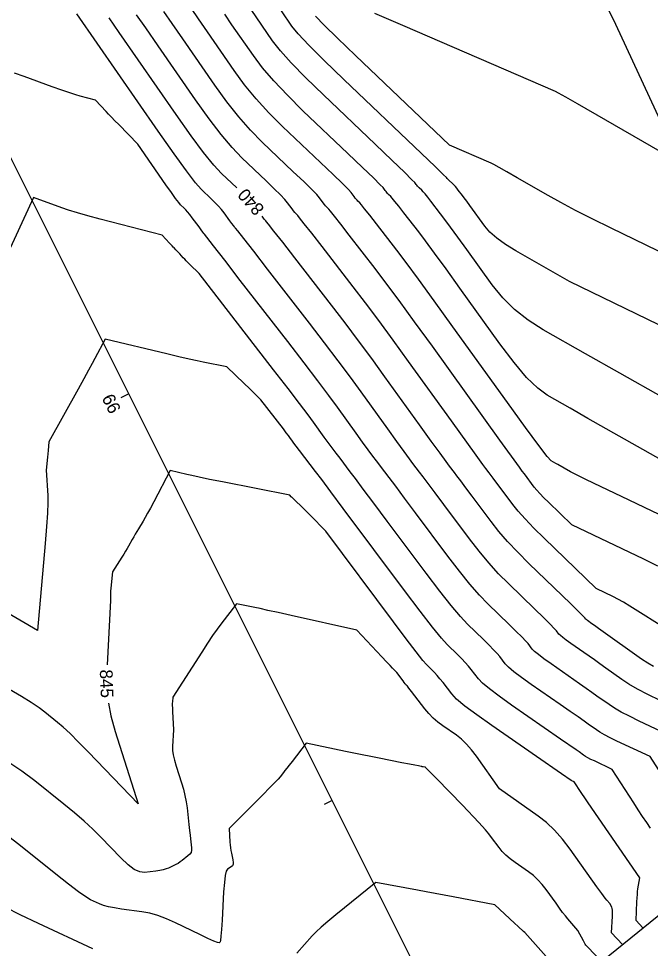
# Model space of a CAD drawing. Extents: x 1715724 to 1716561, y 394063 to 395906.
# Drawn here: x 1716399.3 to 1716468.8, y 394300.9 to 394403.2 of the extents above; entities that cross this region are included whole.
import ezdxf

# ---------------------------------------------------------------- set-up
doc = ezdxf.new("R2010")
doc.units = 0
for name, color, linetype in [('DT_X_Contour_Major', 7, 'Continuous'), ('DT_X_Contour_Minor', 7, 'Continuous'), ('DT_X_TIN_Hull', 7, 'Continuous'), ('GE_P_CL_10', 7, 'Continuous')]:
    doc.layers.add(name, color=color, linetype=linetype)

msp = doc.modelspace()

# ---------------------------------------------------------------- linework, layer by layer
at = {"layer": 'DT_X_Contour_Major'}
for points in [[(1716484.64, 394353.28), (1716465.41, 394364.13), (1716461.63, 394366.28), (1716456.98, 394368.93), (1716455.33, 394369.99), (1716453.84, 394371.16), (1716452.53, 394372.44), (1716451.39, 394373.85), (1716448.58, 394377.75), (1716447.61, 394379.09), (1716446.8, 394380.2), (1716446.16, 394381.06), (1716445.69, 394381.69), (1716444.64, 394383.05), (1716444.28, 394383.5), (1716443.99, 394383.86), (1716443.78, 394384.11), (1716443.63, 394384.27), (1716443.35, 394384.54), (1716443.24, 394384.64), (1716443.15, 394384.73), (1716443.08, 394384.82), (1716443.01, 394384.9), (1716442.86, 394385.11), (1716442.54, 394385.43), (1716441.71, 394386.24), (1716440.35, 394387.54), (1716438.48, 394389.33), (1716432.8, 394394.75), (1716430.85, 394396.64), (1716429.27, 394398.27), (1716428.06, 394399.62), (1716427.21, 394400.71), (1716424.84, 394404.14)], [(1716423.26, 394384.52), (1716421.58, 394386.12), (1716420.73, 394387.04), (1716419.62, 394388.42), (1716418.25, 394390.27), (1716416.61, 394392.59), (1716410.33, 394401.63), (1716409.21, 394403.25)], [(1716469.13, 394331.87), (1716468.51, 394332.23), (1716467.82, 394332.69), (1716467.04, 394333.23), (1716464.12, 394335.32), (1716463.09, 394336.06), (1716462.79, 394336.27), (1716462.2, 394336.68), (1716462, 394336.82), (1716461.85, 394336.94), (1716461.74, 394337.03), (1716461.67, 394337.1), (1716461.56, 394337.24), (1716461.36, 394337.45), (1716460.84, 394337.96), (1716460.02, 394338.76), (1716455.41, 394343.21), (1716454.18, 394344.44), (1716453.07, 394345.62), (1716452.1, 394346.74), (1716451.25, 394347.81), (1716449.18, 394350.6), (1716448.47, 394351.54), (1716447.91, 394352.3), (1716447.49, 394352.86), (1716447.21, 394353.22), (1716446.66, 394353.93), (1716446.31, 394354.42), (1716445.64, 394355.33), (1716444.67, 394356.68), (1716443.39, 394358.45), (1716439.57, 394363.76), (1716438.12, 394365.75), (1716436.66, 394367.72), (1716435.18, 394369.68), (1716433.68, 394371.64), (1716429.65, 394376.84), (1716428.32, 394378.55), (1716427.36, 394379.78), (1716426.77, 394380.53), (1716426.55, 394380.81), (1716426.45, 394380.9), (1716426.39, 394380.97), (1716426.28, 394381.1), (1716426.13, 394381.3), (1716426.06, 394381.4)], [(1716467.97, 394303.11), (1716467.21, 394303.92), (1716467.3, 394305.99), (1716467.32, 394306.42), (1716467.35, 394306.79), (1716467.38, 394307.12), (1716467.42, 394307.4), (1716467.61, 394308.61), (1716461.95, 394316.88), (1716460.87, 394318.46), (1716460.68, 394318.73), (1716460.4, 394319.17), (1716460.13, 394319.3), (1716460.06, 394319.33), (1716459.02, 394320.05), (1716456.24, 394321.98), (1716451.32, 394325.39), (1716449.67, 394326.56), (1716448.38, 394327.53), (1716447.46, 394328.3), (1716446.92, 394328.86), (1716445.97, 394330.1), (1716445.62, 394330.53), (1716445.31, 394330.9), (1716445.03, 394331.22), (1716444.78, 394331.47), (1716444.16, 394332.08), (1716443.75, 394332.54), (1716443.01, 394333.49), (1716441.92, 394334.91), (1716440.5, 394336.8), (1716433.06, 394346.77), (1716431.35, 394348.52), (1716431.01, 394348.87), (1716430.72, 394349.16), (1716430.48, 394349.4), (1716430.29, 394349.58), (1716429.85, 394349.99), (1716429.71, 394350.13), (1716429.59, 394350.24), (1716429.51, 394350.31), (1716429.47, 394350.36), (1716429.39, 394350.43), (1716429.36, 394350.46), (1716429.32, 394350.49), (1716429.29, 394350.52), (1716429.26, 394350.55), (1716429.1, 394350.71), (1716421.71, 394352.18), (1716420.28, 394352.46), (1716419.14, 394352.7), (1716418.31, 394352.87), (1716417.77, 394352.99), (1716415.95, 394353.42), (1716414.13, 394349.99), (1716413.76, 394349.31), (1716413.44, 394348.73), (1716413.18, 394348.26), (1716412.96, 394347.88), (1716412.45, 394347.03), (1716412.26, 394346.72), (1716412.09, 394346.42), (1716411.92, 394346.13), (1716411.76, 394345.85), (1716411.36, 394345.13), (1716411.21, 394344.85), (1716411.03, 394344.55), (1716410.83, 394344.24), (1716410.62, 394343.9), (1716409.59, 394342.28), (1716409.42, 394340.5), (1716409.38, 394340.16), (1716409.36, 394339.88), (1716409.35, 394339.69), (1716409.35, 394339.56), (1716409.37, 394339.14), (1716408.99, 394332.05)], [(1716409.14, 394327.86), (1716409.4, 394326.45), (1716409.87, 394324.74), (1716412.43, 394316.76), (1716406.95, 394322.45), (1716405.86, 394323.57), (1716404.92, 394324.49), (1716404.15, 394325.21), (1716403.54, 394325.73), (1716402.14, 394326.86), (1716401.5, 394327.33), (1716400.64, 394327.9), (1716399.56, 394328.56), (1716398.27, 394329.33)]]:
    msp.add_lwpolyline(points, dxfattribs=at)
at = {"layer": 'DT_X_Contour_Minor'}
for points in [[(1716469.62, 394342.92), (1716468.05, 394343.68), (1716460.13, 394347.46), (1716457.56, 394349.94), (1716457.05, 394350.44), (1716456.62, 394350.89), (1716456.28, 394351.28), (1716456.01, 394351.61), (1716454.93, 394353.06), (1716454.69, 394353.37), (1716454.38, 394353.8), (1716452.22, 394356.79), (1716444.8, 394367.1), (1716442.83, 394369.81), (1716441.13, 394372.15), (1716439.67, 394374.1), (1716438.48, 394375.66), (1716435.64, 394379.32), (1716434.71, 394380.53), (1716434.02, 394381.41), (1716433.58, 394381.96), (1716433.38, 394382.19), (1716433.21, 394382.36), (1716433.13, 394382.44), (1716433.03, 394382.56), (1716432.91, 394382.71), (1716432.77, 394382.9), (1716432.36, 394383.45), (1716432.06, 394383.79), (1716431.49, 394384.38), (1716430.63, 394385.22), (1716429.49, 394386.31), (1716426.07, 394389.57), (1716424.78, 394390.88), (1716423.48, 394392.36), (1716422.17, 394394.01), (1716420.85, 394395.84), (1716417.32, 394400.93), (1716416.14, 394402.63), (1716415.25, 394403.92)], [(1716472.3, 394347.38), (1716465.61, 394350.57), (1716463.37, 394351.64), (1716461.69, 394352.45), (1716460.57, 394353.01), (1716459.99, 394353.3), (1716458.59, 394354.09), (1716458.39, 394354.2), (1716457.86, 394354.51), (1716457.44, 394354.98), (1716456.51, 394356.2), (1716455.05, 394358.18), (1716453.06, 394360.93), (1716447.06, 394369.26), (1716444.99, 394372.12), (1716443.27, 394374.48), (1716441.9, 394376.33), (1716440.88, 394377.67), (1716438.64, 394380.56), (1716437.9, 394381.52), (1716437.34, 394382.23), (1716436.98, 394382.68), (1716436.8, 394382.88), (1716436.59, 394383.08), (1716436.5, 394383.17), (1716436.41, 394383.28), (1716436.3, 394383.41), (1716436.18, 394383.57), (1716435.86, 394384.01), (1716435.56, 394384.34), (1716434.89, 394385), (1716433.87, 394385.99), (1716432.48, 394387.32), (1716428.31, 394391.3), (1716426.8, 394392.8), (1716425.41, 394394.33), (1716424.13, 394395.88), (1716422.97, 394397.46), (1716420.03, 394401.7), (1716419.04, 394403.13), (1716418.27, 394404.25)], [(1716469.7, 394369.48), (1716459.88, 394374.24), (1716453.99, 394377.6), (1716452.83, 394378.31), (1716451.87, 394379), (1716451.11, 394379.66), (1716450.56, 394380.31), (1716448.92, 394382.58), (1716448.57, 394383.06), (1716448.29, 394383.43), (1716448.09, 394383.7), (1716447.63, 394384.29), (1716447.47, 394384.49), (1716447.32, 394384.67), (1716447.18, 394384.83), (1716447.05, 394384.96), (1716446.61, 394385.37), (1716446.53, 394385.46), (1716446.47, 394385.52), (1716446.43, 394385.57), (1716446.36, 394385.66), (1716446.03, 394385.98), (1716445.11, 394386.87), (1716443.59, 394388.32), (1716435.04, 394396.47), (1716432.87, 394398.56), (1716431.2, 394400.24), (1716430.02, 394401.49), (1716429.33, 394402.33), (1716428.17, 394404.01)], [(1716472.03, 394387.27), (1716460.77, 394393.76), (1716459.47, 394394.5), (1716458.67, 394394.96), (1716458.35, 394395.13), (1716441.55, 394402.39), (1716438.45, 394403.73)], [(1716469.88, 394328.13), (1716468.52, 394328.79), (1716467.36, 394329.4), (1716466.4, 394329.95), (1716465.64, 394330.45), (1716463.89, 394331.71), (1716463.24, 394332.17), (1716462.63, 394332.61), (1716462.04, 394333.02), (1716461.48, 394333.41), (1716460.03, 394334.42), (1716459.53, 394334.77), (1716459.15, 394335.06), (1716458.88, 394335.28), (1716458.72, 394335.45), (1716458.44, 394335.81), (1716458.21, 394336.07), (1716457.74, 394336.54), (1716457.02, 394337.25), (1716456.06, 394338.19), (1716453.16, 394340.99), (1716452.08, 394342.08), (1716451, 394343.27), (1716449.94, 394344.55), (1716448.87, 394345.92), (1716446.06, 394349.69), (1716445.1, 394350.98), (1716444.34, 394352), (1716443.77, 394352.75), (1716443.39, 394353.25), (1716442.65, 394354.22), (1716442.27, 394354.73), (1716441.69, 394355.53), (1716440.89, 394356.62), (1716439.89, 394358.01), (1716436.95, 394362.09), (1716435.77, 394363.71), (1716434.43, 394365.51), (1716432.93, 394367.48), (1716431.28, 394369.63), (1716426.65, 394375.59), (1716425.13, 394377.56), (1716424.04, 394378.96), (1716423.37, 394379.82), (1716423.13, 394380.11), (1716423.07, 394380.18), (1716423.02, 394380.24), (1716422.91, 394380.38), (1716422.74, 394380.6), (1716422.52, 394380.9), (1716421.86, 394381.8), (1716421.58, 394382.15), (1716421.26, 394382.51), (1716420.9, 394382.9), (1716420.49, 394383.3), (1716419.34, 394384.4), (1716418.72, 394385.1), (1716417.73, 394386.4), (1716416.37, 394388.28), (1716414.63, 394390.76), (1716405.67, 394403.67)], [(1716469.85, 394336.42), (1716467.4, 394337.98), (1716466.54, 394338.51), (1716465.81, 394338.95), (1716465.21, 394339.3), (1716464.74, 394339.54), (1716462.82, 394340.45), (1716457.09, 394345.99), (1716455.96, 394347.11), (1716455, 394348.11), (1716454.23, 394348.97), (1716453.63, 394349.71), (1716451.48, 394352.6), (1716451.03, 394353.19), (1716450.68, 394353.65), (1716450.34, 394354.11), (1716449.6, 394355.14), (1716446.89, 394358.9), (1716442.18, 394365.43), (1716440.48, 394367.78), (1716438.89, 394369.93), (1716437.43, 394371.89), (1716436.08, 394373.65), (1716432.65, 394378.08), (1716431.51, 394379.54), (1716430.69, 394380.59), (1716430.17, 394381.25), (1716429.97, 394381.5), (1716429.83, 394381.63), (1716429.76, 394381.7), (1716429.66, 394381.83), (1716429.52, 394382.01), (1716429.35, 394382.23), (1716428.86, 394382.9), (1716428.57, 394383.24), (1716428.08, 394383.76), (1716427.38, 394384.44), (1716426.49, 394385.31), (1716423.82, 394387.85), (1716422.76, 394388.96), (1716421.55, 394390.39), (1716420.21, 394392.14), (1716418.73, 394394.21), (1716414.6, 394400.16), (1716413.24, 394402.13), (1716412.23, 394403.58)], [(1716470.8, 394354.14), (1716461.91, 394359.16), (1716459.95, 394360.28), (1716457.42, 394361.72), (1716456.39, 394362.48), (1716455.17, 394363.68), (1716453.79, 394365.31), (1716452.22, 394367.39), (1716447.82, 394373.5), (1716446.3, 394375.61), (1716445.04, 394377.34), (1716444.03, 394378.7), (1716443.29, 394379.68), (1716441.64, 394381.8), (1716441.09, 394382.51), (1716440.67, 394383.04), (1716440.38, 394383.4), (1716440.22, 394383.57), (1716439.97, 394383.81), (1716439.87, 394383.9), (1716439.78, 394384.01), (1716439.69, 394384.12), (1716439.6, 394384.23), (1716439.36, 394384.56), (1716439.05, 394384.88), (1716438.3, 394385.62), (1716437.11, 394386.77), (1716435.48, 394388.32), (1716430.55, 394393.02), (1716428.83, 394394.72), (1716427.34, 394396.3), (1716426.1, 394397.75), (1716425.09, 394399.08), (1716422.74, 394402.47), (1716421.94, 394403.63)], [(1716479.48, 394372.72), (1716474.68, 394375.13), (1716464.46, 394380.09), (1716462.39, 394381.11), (1716460.55, 394382.05), (1716458.93, 394382.91), (1716457.54, 394383.68), (1716454.12, 394385.65), (1716452.99, 394386.3), (1716452.13, 394386.78), (1716451.56, 394387.1), (1716451.27, 394387.25), (1716446.69, 394389.23), (1716436.33, 394399.1), (1716434.36, 394400.99), (1716432.89, 394402.43), (1716431.92, 394403.42)], [(1716472.93, 394323.35), (1716467.54, 394325.88), (1716466.47, 394326.4), (1716465.56, 394326.87), (1716464.82, 394327.3), (1716464.24, 394327.68), (1716462.91, 394328.63), (1716462.36, 394329.02), (1716461.73, 394329.47), (1716461, 394329.98), (1716457.85, 394332.16), (1716457.07, 394332.72), (1716456.46, 394333.18), (1716456.03, 394333.54), (1716455.77, 394333.8), (1716455.32, 394334.39), (1716455.07, 394334.68), (1716454.63, 394335.13), (1716454.02, 394335.74), (1716453.24, 394336.51), (1716450.91, 394338.76), (1716449.98, 394339.72), (1716448.93, 394340.92), (1716447.77, 394342.35), (1716446.5, 394344.02), (1716442.94, 394348.79), (1716441.73, 394350.41), (1716440.76, 394351.7), (1716440.05, 394352.65), (1716439.57, 394353.28), (1716438.64, 394354.5), (1716438.24, 394355.03), (1716437.73, 394355.72), (1716437.12, 394356.56), (1716436.4, 394357.56), (1716434.34, 394360.42), (1716433.41, 394361.68), (1716432.2, 394363.29), (1716430.68, 394365.27), (1716428.87, 394367.62), (1716423.65, 394374.35), (1716421.94, 394376.56), (1716420.71, 394378.15), (1716419.97, 394379.1), (1716419.72, 394379.42), (1716419.69, 394379.45), (1716419.65, 394379.5), (1716419.54, 394379.65), (1716419.36, 394379.9), (1716419.11, 394380.23), (1716418.36, 394381.25), (1716418.09, 394381.6), (1716417.86, 394381.89), (1716417.66, 394382.12), (1716417.49, 394382.29), (1716417.09, 394382.67), (1716416.88, 394382.92), (1716416.54, 394383.36), (1716416.07, 394384.01), (1716415.47, 394384.87), (1716412.38, 394389.33), (1716410.28, 394391.49), (1716409.85, 394391.92), (1716409.48, 394392.31), (1716409.15, 394392.65), (1716408.88, 394392.94), (1716407.71, 394394.18), (1716406.02, 394394.62), (1716405.55, 394394.75), (1716404.89, 394394.97), (1716404.03, 394395.27), (1716402.96, 394395.65), (1716399.85, 394396.78), (1716398.8, 394397.16)], [(1716471.99, 394316.94), (1716468.75, 394321.96), (1716465.09, 394323.68), (1716464.36, 394324.03), (1716463.74, 394324.35), (1716463.23, 394324.64), (1716462.84, 394324.9), (1716461.93, 394325.55), (1716461.49, 394325.87), (1716460.83, 394326.33), (1716459.95, 394326.94), (1716458.86, 394327.7), (1716455.67, 394329.9), (1716454.6, 394330.67), (1716453.77, 394331.29), (1716453.17, 394331.79), (1716452.82, 394332.16), (1716452.2, 394332.96), (1716451.92, 394333.3), (1716451.53, 394333.72), (1716451.03, 394334.23), (1716450.42, 394334.83), (1716448.66, 394336.53), (1716447.88, 394337.36), (1716446.86, 394338.57), (1716445.61, 394340.16), (1716444.12, 394342.13), (1716439.82, 394347.88), (1716438.36, 394349.84), (1716437.19, 394351.39), (1716436.33, 394352.55), (1716435.75, 394353.3), (1716434.63, 394354.78), (1716434.2, 394355.34), (1716433.77, 394355.92), (1716433.34, 394356.51), (1716432.9, 394357.12), (1716431.72, 394358.75), (1716431.11, 394359.57), (1716430.18, 394360.81), (1716428.91, 394362.46), (1716427.32, 394364.52), (1716419.11, 394375.11), (1716418.11, 394376.09), (1716417.9, 394376.3), (1716417.71, 394376.49), (1716417.54, 394376.67), (1716417.38, 394376.83), (1716416.99, 394377.26), (1716416.85, 394377.41), (1716416.73, 394377.53), (1716416.63, 394377.64), (1716416.55, 394377.73), (1716416.36, 394377.93), (1716416.28, 394378.02), (1716416.17, 394378.14), (1716416.03, 394378.28), (1716415.87, 394378.45), (1716415.05, 394379.32), (1716408.24, 394381.1), (1716406.88, 394381.46), (1716405.72, 394381.79), (1716404.76, 394382.09), (1716404, 394382.34), (1716400.91, 394383.46), (1716397.7, 394376.55)], [(1716468.8, 394314.1), (1716468.38, 394314.72), (1716467.93, 394315.39), (1716467.46, 394316.11), (1716466.96, 394316.88), (1716464.58, 394320.56), (1716462.63, 394321.48), (1716462.24, 394321.66), (1716461.91, 394321.83), (1716461.64, 394321.99), (1716461.43, 394322.13), (1716460.95, 394322.47), (1716460.61, 394322.72), (1716458.91, 394323.9), (1716453.5, 394327.64), (1716452.13, 394328.61), (1716451.07, 394329.41), (1716450.32, 394330.05), (1716449.87, 394330.51), (1716449.08, 394331.53), (1716448.77, 394331.91), (1716448.42, 394332.31), (1716448.03, 394332.73), (1716447.6, 394333.15), (1716446.41, 394334.31), (1716445.78, 394335), (1716444.79, 394336.22), (1716443.45, 394337.96), (1716441.74, 394340.23), (1716434.99, 394349.27), (1716433.62, 394351.09), (1716432.61, 394352.45), (1716431.94, 394353.33), (1716430.17, 394355.65), (1716429.82, 394356.11), (1716429.56, 394356.45), (1716429.4, 394356.67), (1716429.1, 394357.08), (1716428.95, 394357.29), (1716428.71, 394357.6), (1716428.39, 394358.02), (1716425.92, 394361.22), (1716424.65, 394362.46), (1716424.09, 394363.01), (1716422.17, 394364.85), (1716419.57, 394365.37), (1716418.91, 394365.5), (1716418.02, 394365.7), (1716416.9, 394365.96), (1716415.56, 394366.27), (1716408.78, 394367.87), (1716407.66, 394365.77), (1716407.36, 394365.22), (1716406.95, 394364.48), (1716406.43, 394363.53), (1716405.8, 394362.39), (1716402.57, 394356.61), (1716402.49, 394355.65), (1716402.42, 394354.89), (1716402.28, 394353.46), (1716402.46, 394350.68), (1716402.47, 394349.91), (1716402.43, 394348.76), (1716402.33, 394347.26), (1716402.18, 394345.39), (1716401.34, 394335.82), (1716389.81, 394342.56)], [(1716465.71, 394301.28), (1716464.52, 394302.56), (1716464.6, 394304.42), (1716464.61, 394304.78), (1716464.6, 394305.07), (1716464.58, 394305.27), (1716464.54, 394305.39), (1716464.33, 394305.79), (1716463.99, 394306.18), (1716463.82, 394306.4), (1716463.46, 394306.89), (1716462.91, 394307.65), (1716459.95, 394311.79), (1716459.11, 394312.89), (1716458.25, 394313.86), (1716457.36, 394314.7), (1716456.45, 394315.41), (1716452.18, 394318.43), (1716449.65, 394322), (1716449.11, 394322.72), (1716448.56, 394323.34), (1716448, 394323.87), (1716447.44, 394324.31), (1716445.94, 394325.35), (1716445.39, 394325.76), (1716444.88, 394326.21), (1716444.41, 394326.69), (1716443.97, 394327.22), (1716442.48, 394329.14), (1716442.21, 394329.49), (1716442.04, 394329.71), (1716441.96, 394329.79), (1716441.91, 394329.85), (1716441.87, 394329.89), (1716441.8, 394329.98), (1716441.7, 394330.11), (1716441.57, 394330.29), (1716440.89, 394331.2), (1716440.54, 394331.55), (1716440.41, 394331.7), (1716440.14, 394331.98), (1716439.75, 394332.39), (1716439.22, 394332.95), (1716436.49, 394335.86), (1716429.24, 394337.48), (1716427.83, 394337.8), (1716426.69, 394338.05), (1716425.84, 394338.24), (1716425.26, 394338.36), (1716423.23, 394338.78), (1716421.51, 394336.55), (1716421.1, 394336), (1716420.61, 394335.3), (1716420.05, 394334.46), (1716419.41, 394333.47), (1716416.23, 394328.51), (1716416.18, 394327.99), (1716416.17, 394327.84), (1716416.17, 394327.61), (1716416.18, 394327.3), (1716416.2, 394326.91), (1716416.3, 394324.9), (1716416.2, 394323.07), (1716416.21, 394322.64), (1716416.28, 394322.14), (1716416.41, 394321.56), (1716416.6, 394320.9), (1716417.19, 394319.07), (1716417.4, 394318.38), (1716417.56, 394317.69), (1716417.7, 394317), (1716417.79, 394316.31), (1716418, 394314.48), (1716418.07, 394313.85), (1716418.13, 394313.32), (1716418.18, 394312.9), (1716418.22, 394312.59), (1716418.3, 394311.91), (1716418.3, 394311.66), (1716418.23, 394311.43), (1716418.1, 394311.22), (1716417.89, 394311.03), (1716417.26, 394310.54), (1716417.03, 394310.37), (1716416.8, 394310.22), (1716416.57, 394310.08), (1716416.34, 394309.97), (1716415.74, 394309.7), (1716415.49, 394309.6), (1716415.17, 394309.51), (1716414.8, 394309.44), (1716414.36, 394309.37), (1716413.11, 394309.22), (1716412.59, 394309.27), (1716411.99, 394309.56), (1716411.3, 394310.07), (1716410.52, 394310.81), (1716408.31, 394313.1), (1716407.44, 394313.97), (1716406.47, 394314.87), (1716405.41, 394315.79), (1716404.25, 394316.74), (1716401.04, 394319.3), (1716399.61, 394320.36), (1716397.73, 394321.62)], [(1716463.38, 394299.47), (1716461.89, 394300.99), (1716461.75, 394301.14), (1716461.71, 394301.19), (1716461.68, 394301.23), (1716461.62, 394301.33), (1716461.42, 394301.71), (1716460.81, 394302.83), (1716459.7, 394304.13), (1716459.44, 394304.44), (1716459.13, 394304.83), (1716458.79, 394305.29), (1716458.4, 394305.83), (1716457.31, 394307.35), (1716456.88, 394307.9), (1716456.41, 394308.41), (1716455.91, 394308.87), (1716455.37, 394309.28), (1716453.89, 394310.33), (1716453.36, 394310.73), (1716452.89, 394311.13), (1716452.49, 394311.54), (1716452.15, 394311.95), (1716451.31, 394313.06), (1716450.99, 394313.48), (1716450.65, 394313.89), (1716450.29, 394314.3), (1716449.91, 394314.71), (1716448.1, 394316.62), (1716445.28, 394319.51), (1716444.75, 394320.05), (1716444.37, 394320.44), (1716444.13, 394320.67), (1716444.05, 394320.76), (1716444.02, 394320.79), (1716443.78, 394320.83), (1716443.73, 394320.84), (1716443.68, 394320.85), (1716443.63, 394320.86), (1716443.57, 394320.87), (1716443.43, 394320.9), (1716443.26, 394320.94), (1716442.88, 394321.01), (1716442.27, 394321.13), (1716441.44, 394321.29), (1716438.95, 394321.78), (1716438.01, 394321.97), (1716437.08, 394322.16), (1716436.15, 394322.35), (1716435.22, 394322.54), (1716430.9, 394323.43), (1716429.35, 394321.42), (1716429.04, 394321.02), (1716428.78, 394320.69), (1716428.57, 394320.42), (1716428.41, 394320.21), (1716428.04, 394319.75), (1716427.82, 394319.49), (1716427.43, 394319.08), (1716426.88, 394318.52), (1716426.16, 394317.79), (1716422.42, 394314.04), (1716422.52, 394312.56), (1716422.54, 394312.24), (1716422.58, 394311.94), (1716422.63, 394311.64), (1716422.68, 394311.35), (1716422.84, 394310.59), (1716422.88, 394310.33), (1716422.86, 394310.12), (1716422.79, 394309.95), (1716422.66, 394309.83), (1716422.26, 394309.59), (1716422.11, 394309.36), (1716421.99, 394308.87), (1716421.9, 394308.11), (1716421.82, 394307.08), (1716421.64, 394303.98), (1716421.58, 394302.95), (1716421.52, 394302.21), (1716421.47, 394301.75), (1716421.42, 394301.57), (1716421.31, 394301.47), (1716421.14, 394301.5), (1716420.74, 394301.66), (1716420.09, 394301.96), (1716419.21, 394302.38), (1716416.52, 394303.68), (1716415.54, 394304.13), (1716414.59, 394304.47), (1716413.69, 394304.73), (1716412.82, 394304.89), (1716410.58, 394305.19), (1716409.8, 394305.31), (1716409.13, 394305.44), (1716408.59, 394305.59), (1716408.16, 394305.76), (1716407.18, 394306.21), (1716406.67, 394306.52), (1716405.86, 394307.09), (1716404.76, 394307.92), (1716403.37, 394309.02), (1716399.27, 394312.29), (1716397.7, 394313.5)], [(1716457.3, 394299.98), (1716454.97, 394302.61), (1716454.83, 394302.73), (1716454.25, 394303.26), (1716453.84, 394303.64), (1716451.66, 394305.66), (1716447.07, 394306.54), (1716446.09, 394306.73), (1716445.11, 394306.91), (1716444.12, 394307.1), (1716443.14, 394307.28), (1716438.56, 394308.11), (1716434.16, 394304.56), (1716433.29, 394303.84), (1716432.57, 394303.21), (1716431.99, 394302.67), (1716431.56, 394302.23), (1716429.88, 394300.35)], [(1716407.41, 394300.81), (1716401.45, 394303.6), (1716399.43, 394304.57), (1716397.85, 394305.37)]]:
    msp.add_lwpolyline(points, dxfattribs=at)
at = {"layer": 'DT_X_TIN_Hull'}
msp.add_lwpolyline([(1716463.55, 394299.53), (1716471.86, 394306.26), (1716483.85, 394306.75), (1716504.79, 394314.54), (1716501.89, 394321.94), (1716496.82, 394331.94), (1716489.52, 394351.03), (1716488, 394358.9), (1716476.67, 394377.28), (1716464.97, 394402.5), (1716450.77, 394431.32), (1716438.69, 394455.43), (1716425.17, 394480.67), (1716411.91, 394506.87), (1716399.57, 394530.29)], dxfattribs=at)
at = {"layer": 'GE_P_CL_10'}
for p, q in [((1716447.81, 394289.08), (1716249.46, 394685.42)), ((1716411.38, 394361.87), (1716410.49, 394361.42)), ((1716433.76, 394317.15), (1716432.87, 394316.71))]:
    msp.add_line(p, q, dxfattribs=at)

# ---------------------------------------------------------------- texts
at = {"layer": 'DT_X_Contour_Major'}
for s, rotation, p in [('840', 131.8975, (1716426.38, 394382.28)), ('845', 272.1614, (1716408.19, 394331.52))]:
    msp.add_text(s, height=1.4, rotation=rotation, dxfattribs=at).set_placement(p)
at = {"layer": 'GE_P_CL_10'}
msp.add_text('99', height=1.4, rotation=116.5857, dxfattribs=at).set_placement((1716410.56, 394360.17))

doc.saveas('drawing.dxf')
